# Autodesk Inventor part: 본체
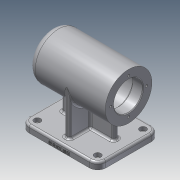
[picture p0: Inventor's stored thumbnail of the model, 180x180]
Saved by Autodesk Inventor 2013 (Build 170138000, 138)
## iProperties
Created: 2020-10
Part Number: 본체
Material: 알루미늄 6061
Document SubType Name: Modeling
Designer: 19
Density: 2.71 g/cm^3
Mass: 1030.08 g
Surface Area: 757.95 cm^2
Volume: 380.102 cm^3
Author: 19
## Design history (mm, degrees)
sketch "스케치1"
  geometry: C1 r 34 at (0, 0); 1 further point
  constraints: 1 centre point, 1 coincident
  dimensions: "d0" = 68 diameter of C1
extrude "돌출1" new body sketch "스케치1" stored distance "d1" = 112; taper "d2" = 0 deg
sketch "스케치2"
  geometry: L1 (34, -56)-(-34, -56) reference; L2 (-34, -56)-(-34, 56) reference; L3 (-34, 56)-(34, 56) reference; L4 (34, 56)-(34, -56) reference; L5 (0, 56)-(0, -56); L6 (0, 50)-(10.5, 50); L7 (10.5, 50)-(10.5, 47); L8 (10.5, 47)-(16, 47); L9 (16, 47)-(16, 43); L10 (16, 43)-(17.5, 43); L11 (17.5, 43)-(17.5, 25); L12 (17.5, 25)-(21, 25); L13 (21, 25)-(21, 13); L14 (21, 13)-(24, 13); L15 (24, 13)-(24, -41); L16 (24, -41)-(21, -41); L17 (21, -41)-(21, -56); L18 (0, -56)-(21, -56); 1 further point
  constraints: 28 end point, 8 parallel, 5 perpendicular, 2 midpoint, 2 point on line
  dimensions: "d20" = 42 diameter of L17 L5; "d22" = 15 distance between parallel lines of L16 L1; "d23" = 48 diameter of L15 L5; "d24" = 54 distance between parallel lines of L14 L16; "d25" = 42 diameter of L13 L5; "d26" = 12 distance between parallel lines of L14 L12; "d28" = 35 diameter of L11 L5; "d29" = 18 distance between parallel lines of L12 L10; "d30" = 32 diameter of L9 L5; "d31" = 4 distance between parallel lines of L10 L8; "d32" = 21 diameter of L7 L5; "d33" = 3 distance between parallel lines of L8 L6
revolve "회전1" sketch "스케치2" stored, may be unused: angle "d34" = 90 deg
node "작업 평면1"
sketch "스케치3"
  geometry: L1 (-34, -56)-(34, -56) reference; L2 (33, 56)-(-33, 56); L3 (-45, 44)-(-45, -44); L4 (-33, -56)-(33, -56); L5 (45, -44)-(45, 44); L6 (45, 56)-(-45, -56); L7 (-45, 56)-(45, -56); A1 r 12 centre (33, 44) between (45, 44) and (33, 56); A2 r 12 centre (33, -44) between (33, -56) and (45, -44); A3 r 12 centre (-33, -44) between (-45, -44) and (-33, -56); A4 r 12 centre (-33, 44) between (-33, 56) and (-45, 44); 3 further points
  constraints: 12 end point, 8 point on circle, 8 point on line, 8 tangent, 4 centre point, 4 midpoint, 3 equal radius, 2 parallel, 1 horizontal, 1 perpendicular
  dimensions: "d36" = 90 distance of L7.end L6.end; "d37" = 112 distance of L6.end L7.start; "d38" = 12 radius of A1
extrude "돌출2" join sketch "스케치3" distance "d39" = 10; taper "d40" = 0 deg
sketch "스케치4"
  geometry: L1 (34, -4)-(-34, -4); L2 (-34, -4)-(-34, 4); L3 (-34, 4)-(34, 4); L4 (34, 4)-(34, -4); L5 (34, -4)-(-34, 4); L6 (-34, -4)-(34, 4); 1 further point
  constraints: 12 end point, 2 midpoint, 2 parallel, 1 horizontal, 1 perpendicular
  dimensions: "d45" = 68 distance of L2.end L3.end; "d46" = 8 distance of L1.end L2.end
extrude "돌출3" join sketch "스케치4" stored distance "d47" = 10; taper "d48" = 0 deg
sketch "스케치6"
  geometry: L1 (33, 56)-(-33, 56) reference; L2 (-4, -38)-(4, -38); L3 (4, -38)-(4, 38); L4 (4, 38)-(-4, 38); L5 (-4, 38)-(-4, -38); L6 (-4, -38)-(4, 38); L7 (4, -38)-(-4, 38); 1 further point
  constraints: 12 end point, 2 midpoint, 2 parallel, 1 horizontal, 1 perpendicular
  dimensions: "d73" = 18 distance between parallel lines of L4 L1; "d74" = 8 distance between parallel lines of L3 L5
extrude "돌출5" join sketch "스케치6" stored distance "d56" = 10; taper "d57" = 0 deg
sketch "스케치7"
  geometry: L1 (88, 0)-(0, 0) reference; L2 (100, 0)-(100, 10) reference; 2 further points
  constraints: 1 other
  dimensions: "d58" = 3 distance from line of L1 point (44, 3); "d59" = 56 distance from line of L2 point (44, 3)
feature "엠보싱1" sketch "스케치7" dims "d60" = 0.5, "d61" = 0
sketch "스케치8" dims "d62" = 52
  geometry: C1 r 21 at (0, 0) reference; C2 r 34 at (0, 0) reference; 2 further points
  constraints: 2 vertical alignment, 1 coincident, 2 other
hole "구멍1" sketch "스케치8" at (0, 26) diameter "d63" = 3.242; stored, may be unused: countersink angle "d67" = 90 deg, drill point angle "d69" = 118 deg; dims "d64" = 8, "d65" = 4, "d66" = 2, "d68" = 11
sketch "스케치9"
  geometry: 1 further point
fillet "모깎기1" dims "d75" = 3
fillet "모깎기2" dims "d76" = 0.3
chamfer "모따기1" distance "d77" = 1; stored, may be unused: second distance "d78" = 2, angle "d79" = 45 deg
fillet "모깎기3" dims "d80" = 10
sketch "스케치10"
  geometry: C1 r 4.75 at (-33, 44); C2 r 4.75 at (33, 44); C3 r 4.75 at (-33, -44); C4 r 4.75 at (33, -44); A1 r 12 centre (-33, -44) between (-45, -44) and (-33, -56) reference; A2 r 12 centre (33, -44) between (33, -56) and (45, -44) reference; A3 r 12 centre (33, 44) between (45, 44) and (33, 56) reference; A4 r 12 centre (-33, 44) between (-33, 56) and (-45, 44) reference; 1 further point
  constraints: 4 centre point, 4 coincident
  dimensions: "d81" = 9.5 diameter of C1; "d82" = 9.5 diameter of C2; "d83" = 9.5 diameter of C3; "d84" = 9.5 diameter of C4
extrude "돌출6" cut sketch "스케치10" distance "d85" = 5.4; taper "d86" = 0 deg
sketch "스케치11"
  geometry: C1 r 2.75 at (33, 44); C2 r 2.75 at (33, -44); C3 r 2.75 at (-33, 44); C4 r 2.75 at (-33, -44); A1 r 12 centre (-33, -44) between (-45, -44) and (-33, -56) reference; A2 r 12 centre (33, -44) between (33, -56) and (45, -44) reference; A3 r 12 centre (33, 44) between (45, 44) and (33, 56) reference; A4 r 12 centre (-33, 44) between (-33, 56) and (-45, 44) reference; 1 further point
  constraints: 4 centre point, 4 coincident
  dimensions: "d87" = 5.5 diameter of C1; "d88" = 5.5 diameter of C2; "d89" = 5.5 diameter of C3; "d90" = 5.5 diameter of C4
extrude "돌출7" cut sketch "스케치11" distance "d91" = 10; taper "d92" = 0 deg
fillet "모깎기4" dims "d93" = 3
fillet "모깎기5" dims "d94" = 3
fillet "모깎기6" dims "d95" = 3
fillet "모깎기7" dims "d96" = 3
node "솔리드1"
pattern_circular "원형 패턴1" dims angle "d71" = 360 deg
node "절단 모서리 투영1"
other parameters: "d35" = -74
